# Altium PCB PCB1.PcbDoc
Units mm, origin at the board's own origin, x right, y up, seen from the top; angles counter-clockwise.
Board outline 160 x 100 mm, 4 copper layers (Top Layer, Top inner, Bottom inner, Bottom Layer), stack 1.538 mm thick; 114 components, 70 nets, 377 pads, 75 vias.
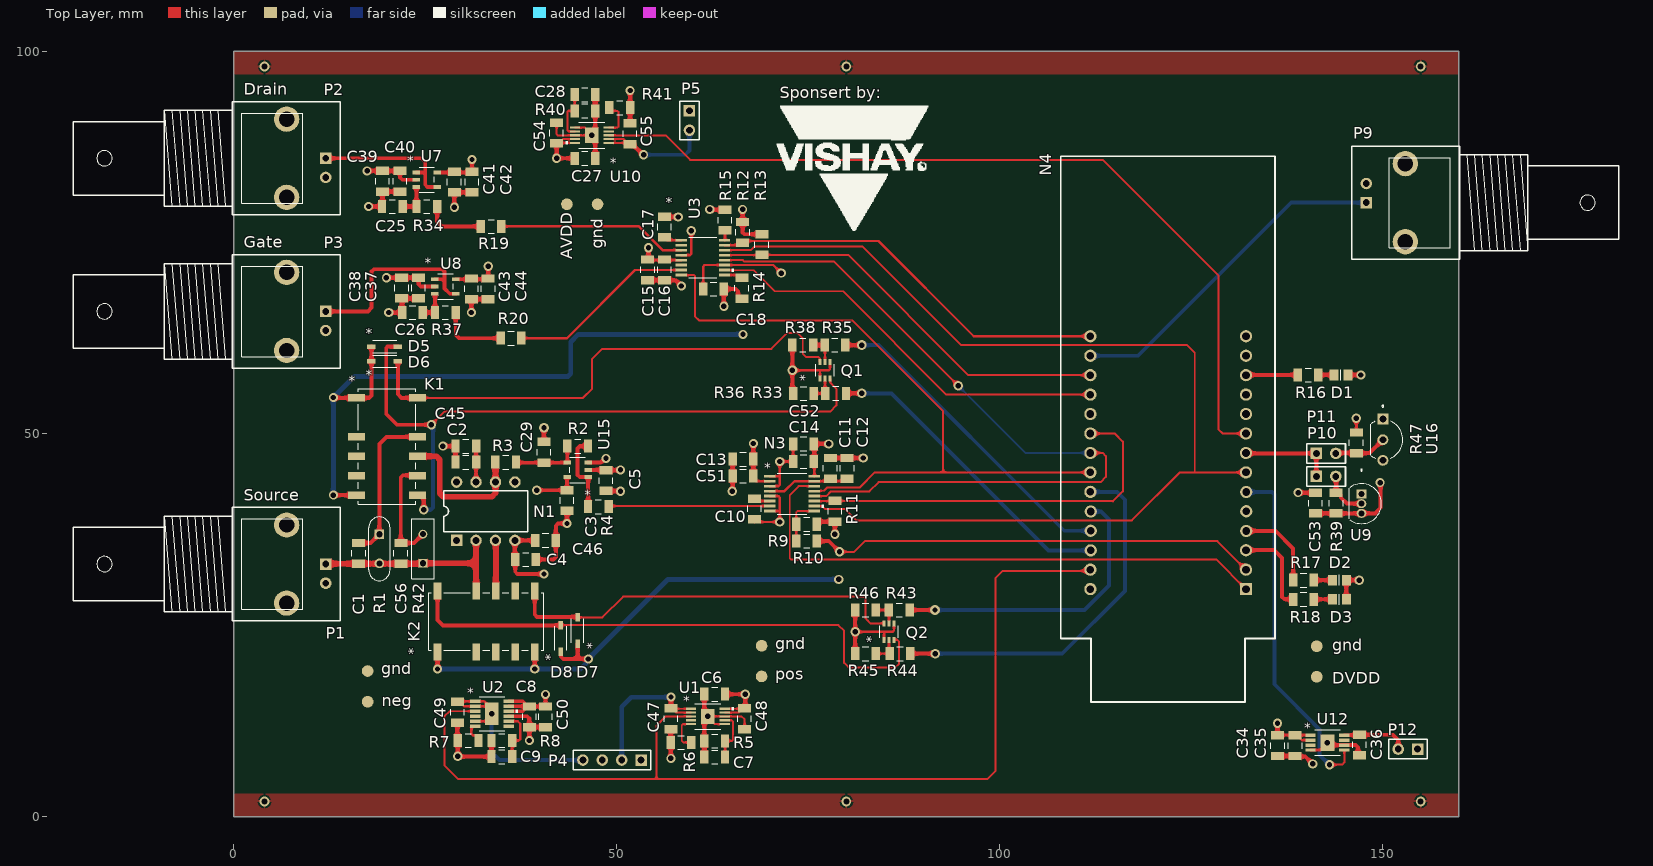
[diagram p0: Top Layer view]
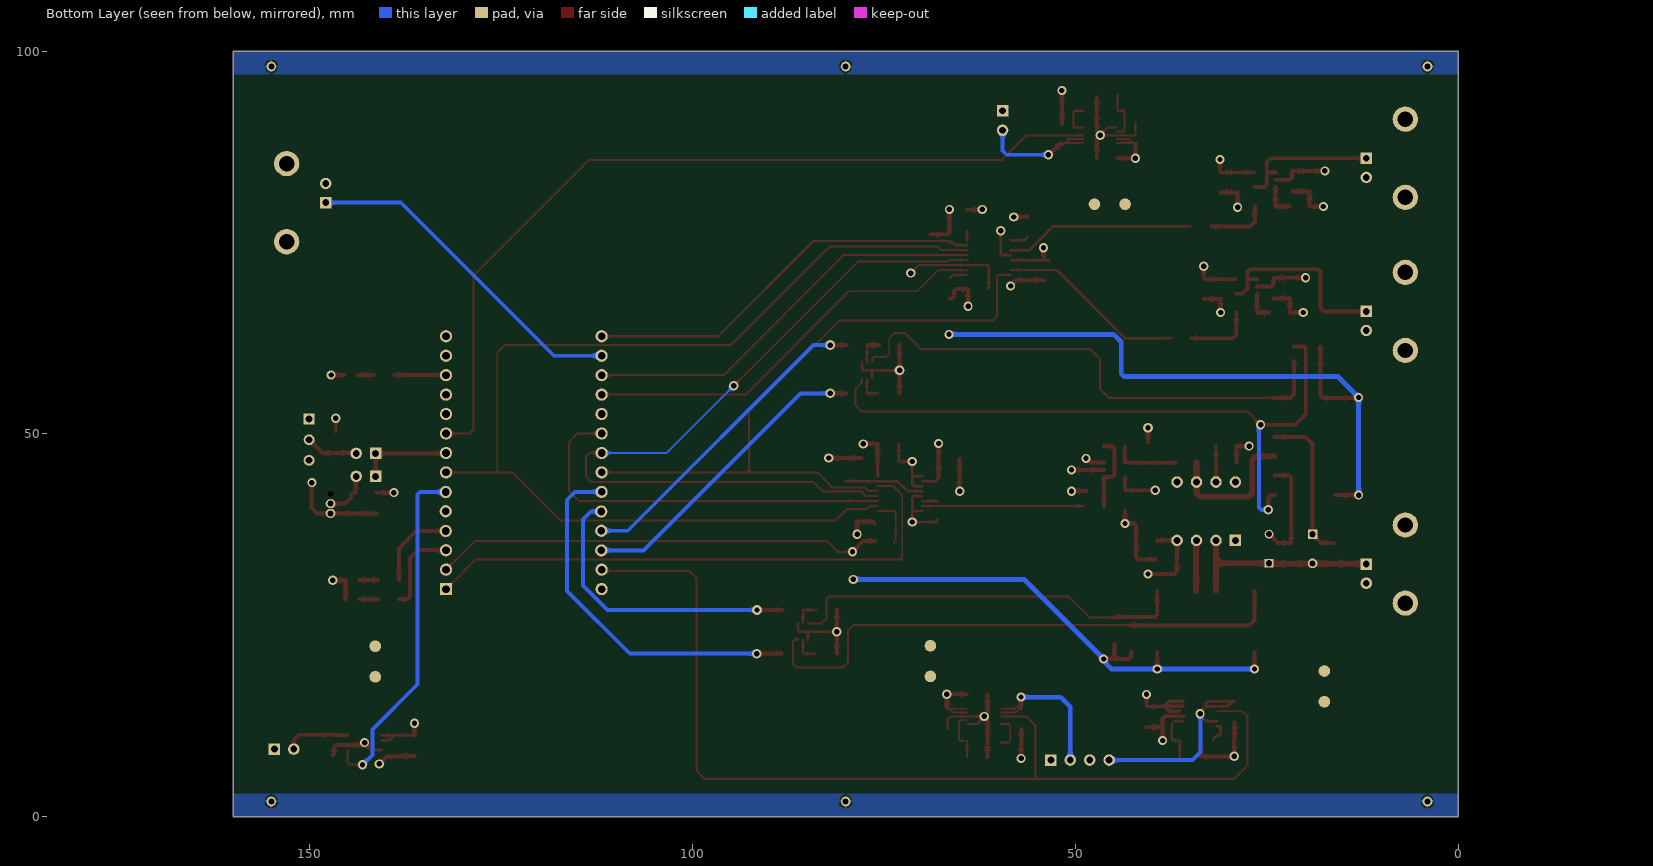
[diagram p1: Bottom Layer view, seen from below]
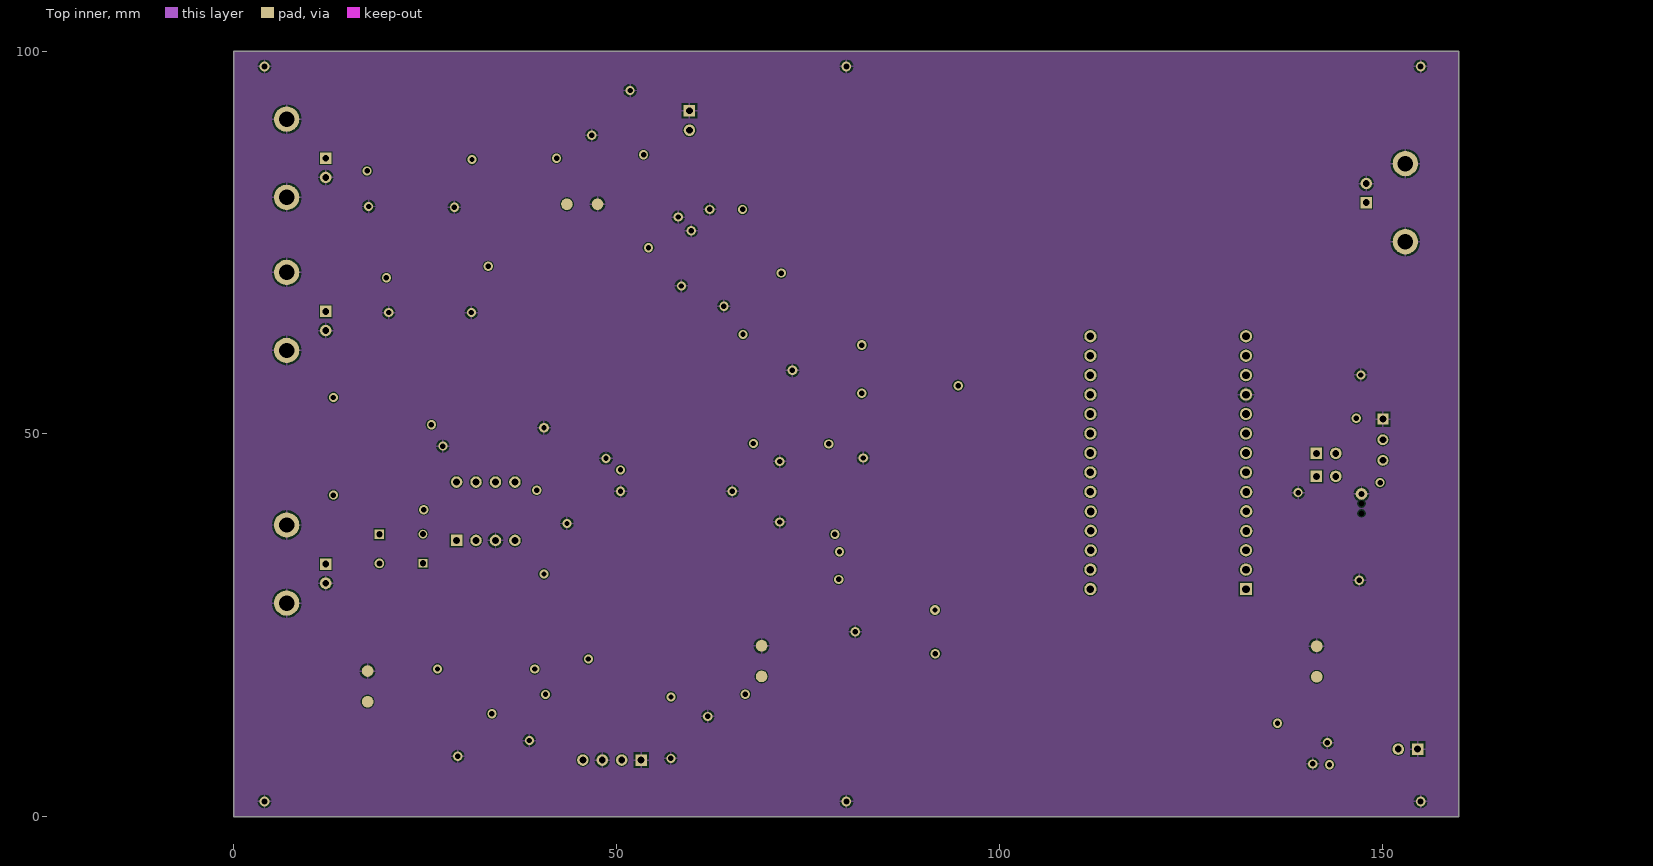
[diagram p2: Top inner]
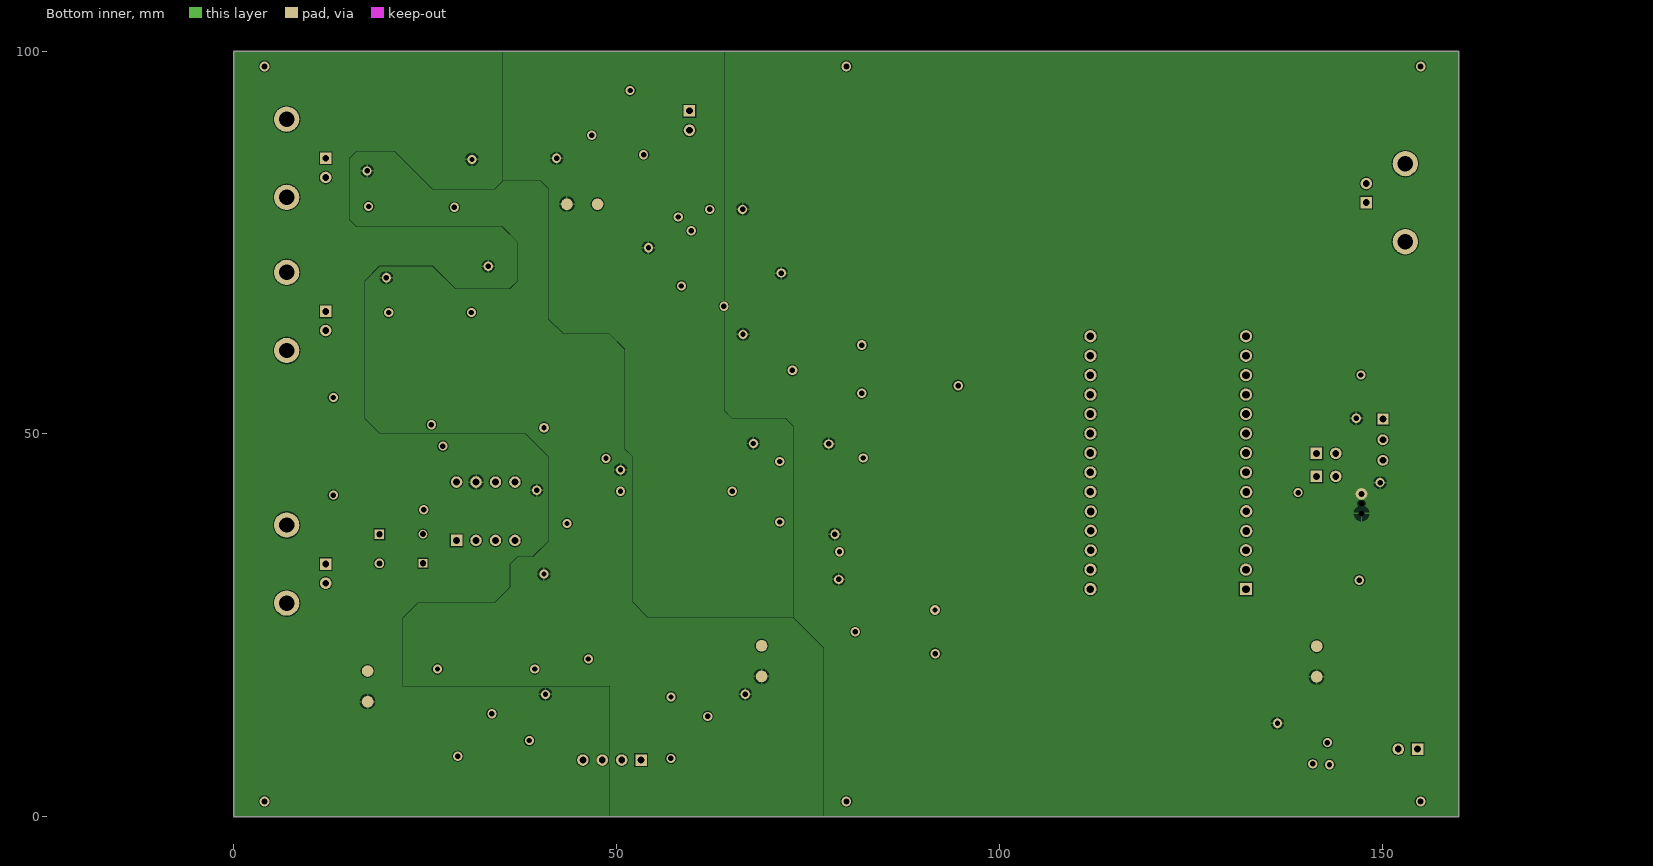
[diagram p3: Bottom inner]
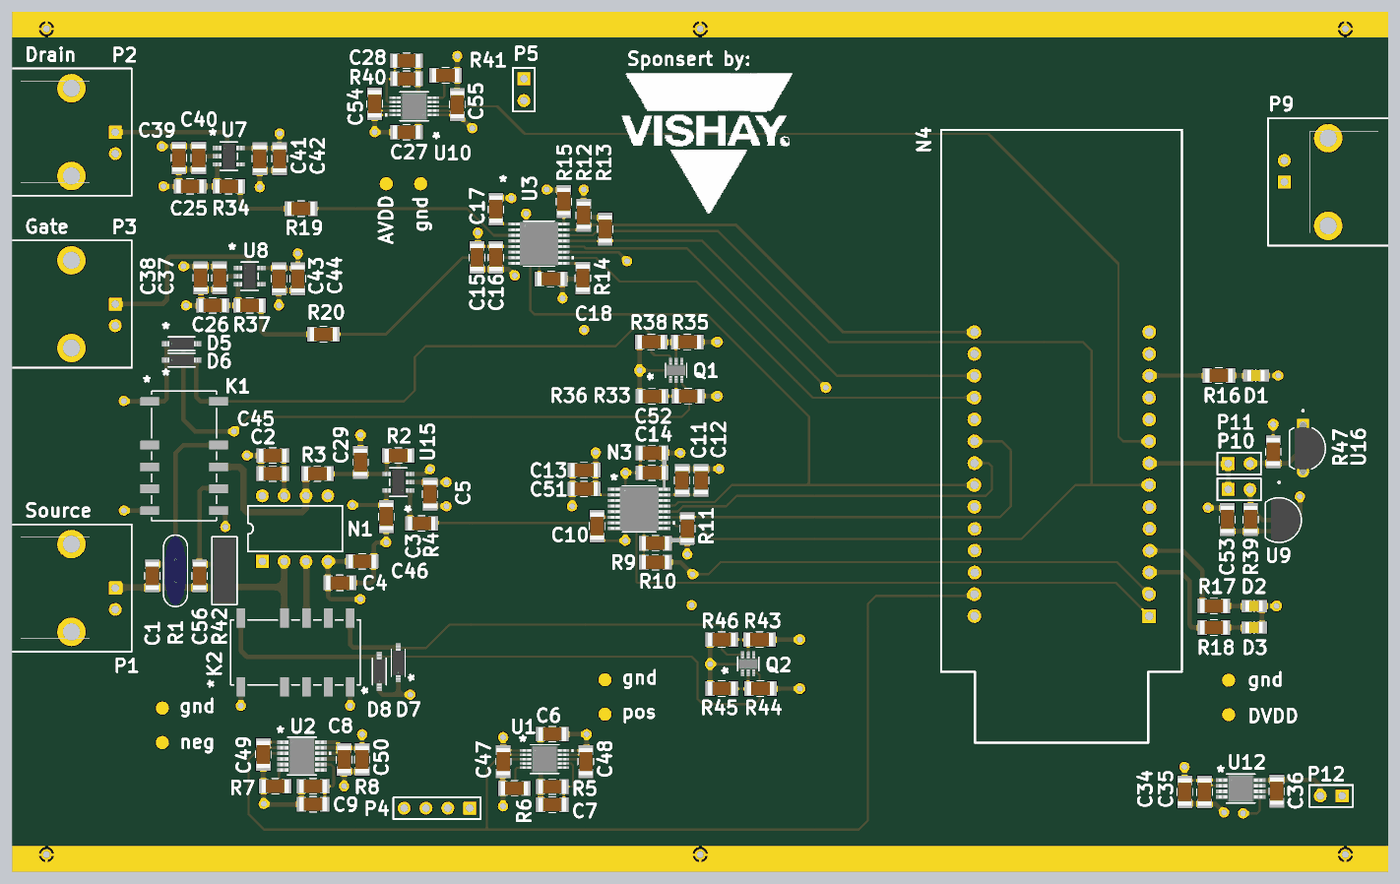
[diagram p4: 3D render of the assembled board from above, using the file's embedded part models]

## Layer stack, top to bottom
Top Solder: solder mask 0.0102, Solder Resist, Dk 3.5
Top Layer: signal copper 0.0356
Dielectric 4: prepreg 0.1524, PP-006, Dk 4.4
Top inner: signal copper 0.035
Dielectric 1: dielectric 1.0922, FR-4, Dk 4.8
Bottom inner: signal copper 0.035
Dielectric 5: prepreg 0.1524, PP-006, Dk 4.4
Bottom Layer: signal copper 0.0356
Bottom Solder: solder mask 0.0102, Solder Resist, Dk 3.5

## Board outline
0,0 160,0 160,100 0,100

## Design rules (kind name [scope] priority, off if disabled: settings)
Clearance [All] p1: gap=0.127 ignorepadtopadclearanceinfootprint=TRUE except(0.025: THPad-THPad)
MinimumSolderMaskSliver THT_21-0248A_Q3-1_MXM [HasFootprint('21-0248A_Q3-1_MXM')] p1: minsoldermaskwidth=0
MinimumSolderMaskSliver [All] p2: minsoldermaskwidth=0.127
PolygonConnect [All] p1: connectstyle=Relief reliefconductorwidth=0.254 reliefentries=4 polygonreliefangle="90 Angle" airgapwidth=0.254
RoutingVias [All] p1: holewidth=0.6 width=1.2 viastyle="Through Hole" minholewidth=0.3 minwidth=0.6 maxholewidth=1 maxwidth=2
SilkToSolderMaskClearance SilkToSolderMaskClearance_1 [HasFootprint('BNC_RA CON')] p1: minsilkscreentomaskgap=0 clearancetoexposedcopper=TRUE
SilkToSolderMaskClearance [IsPad] p2: minsilkscreentomaskgap=0.127 clearancetoexposedcopper=TRUE
SolderMaskExpansion [All] p1: expansion=0.102 istentingtop=FALSE
Width Source [InNet('M_source')] p1: maxlimit=2.54 minlimit=0.254 preferedwidth=0.762
Width Width_1 [All] p2: maxlimit=0.762 minlimit=0.254 preferedwidth=0.762
28 further rules are at their usual default settings.

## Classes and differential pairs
component class U_Cal: Q1 Q2 R33 R35 R36 R38 R43 R44 R45 R46
component class U_Digital_Psu: C34 C35 C36 U12
component class U_Analog_PSU_5: C27 C28 C54 R40 R41 U10
component class U_Temp_Sensors: C53 P10 P11 R39 R47 U9 U16
component class U_Source_TIA: C1 C2 C3 C4 C5 C29 C45 C46 C56 D5 D6 D7 D8 K1 K2 N1 R1 R2 R3 R4 R42 U15
component class U_OPV_psu: C6 C7 C8 C9 C47 C48 C49 C50 R5 R6 R7 R8 U1 U2
component class U_DAC_Buffer_Filter: C25 C26 C37 C38 C39 C40 C41 C42 C43 C44 R19 R20 R34 R37 U7 U8
component class U_CortexM3_dev: D1 D2 D3 N4 R16 R17 R18
component class U_ADC_8681: C10 C11 C12 C13 C14 C51 C52 N3 R9 R10 R11
component class U_AD_5689_DAC: C15 C16 C17 C18 R12 R13 R14 R15 U3
component class Top_Sheet: C55 P1 P2 P3 P4 P5 P9 P12

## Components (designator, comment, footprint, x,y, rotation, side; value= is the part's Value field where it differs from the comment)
C1 "22pF" C1206-KUE 16.3,34.4 r90 top
C2 "100nF" C1206-KUE 30.3,46.3 r0 top
C3 "100nF" C1206-KUE 43.503,41.3 r90 top
C4 "100nF" C1206-KUE 38.1,33.6 r180 top
C5 "100nF" C1206-KUE 48.603,43.9 r90 top
C6 "10uF" C1206-KUE 62.8,16 r0 top
C7 "4.7uF" C1206-KUE 62.8,7.8 r0 top
C8 "10uF" C1206-KUE 38.6,13.049 r90 top
C9 "4.7uF" C1206-KUE 35,7.849 r0 top
C10 "10uF" C1206-KUE 68,40.2 r90 top
C11 "100nF" C1206-KUE 77.9,45.5 r270 top
C12 "10uF" C1206-KUE 80.1,45.5 r270 top
C13 "100nF" C1206-KUE 66.5,46.7 r0 top
C14 "100nF" C1206-KUE 74.4,46.4 r0 top
C15 "10uF" C1206-KUE 54.05,71.425 r90 top
C16 "100nF" C1206-KUE 56.25,71.425 r90 top
C17 "100nF" C1206-KUE 56.25,77.025 r270 top
C18 "100nF" C1206-KUE 62.65,68.925 r180 top
C25 "1uF" C1206-KUE 20.7,79.7 r0 top
C26 "1uF" C1206-KUE 23.324,65.85 r0 top
C27 "10uF" C1206-KUE 45.849,86 r180 top
C28 "4.7uF" C1206-KUE 45.849,94.3 r180 top
C29 "" C1206-KUE 40.5,47.6 r270 top
C34 "100nF" C1206-KUE 136.323,9.279 r90 top
C35 "10uF" C1206-KUE 138.623,9.279 r90 top
C36 "4.7uF" C1206-KUE 147.023,9.379 r90 top
C37 "100nF" C1206-KUE 24.124,69.05 r90 top
C38 "1uF" C1206-KUE 21.924,69.05 r90 top
C39 "100nF" C1206-KUE 19.4,83 r90 top
C40 "1uF" C1206-KUE 21.7,83 r90 top
C41 "100nF" C1206-KUE 28.8,82.9 r90 top
C42 "1uF" C1206-KUE 31.1,82.9 r90 top
C43 "100nF" C1206-KUE 31.024,68.95 r90 top
C44 "1uF" C1206-KUE 33.224,68.95 r90 top
C45 "10uF" C1206-KUE 30.3,48.4 r0 top
C46 "10uF" C1206-KUE 40.7,36.1 r0 top
C47 "10uF" C1206-KUE 57.1,12.8 r90 top
C48 "100nF" C1206-KUE 66.7,12.8 r90 top
C49 "10uF" C1206-KUE 29.2,13.649 r90 top
C50 "100nF" C1206-KUE 40.7,13.049 r90 top
C51 "10uF" C1206-KUE 66.5,44.5 r0 top
C52 "10uF" C1206-KUE 74.4,48.7 r0 top
C53 "1uF" C1206-KUE 141.277,40.961 r270 top
C54 "100nF" C1206-KUE 42.149,89.3 r270 top
C55 "100nF" C1206-KUE 51.749,89.2 r270 top
C56 "22pF" C1206-KUE 21.8,34.4 r90 top
D1 "GREEN" 6-0805_N-KUE 144.6,57.7 r0 top
D2 "GREEN" 6-0805_N-KUE 144.4,30.9 r0 top
D3 "RED" 6-0805_N-KUE 144.4,28.4 r0 top
D5 "1N4148W-7" SOD123_DIO 19.7,61.4 r0 top
D6 "1N4148W-7" SOD123_DIO 19.7,59.5 r0 top
D7 "1N4148W-7" SOD123_DIO 44.9,24.3 r90 top
D8 "1N4148W-7" SOD123_DIO 42.7,23.3 r90 top
K1 "G6SK-2F-TR DC3" "RELAY_G6SK-2F DC3_OMR" 24,42 r0 top
K2 "G6SK-2F-TR DC3" "RELAY_G6SK-2F DC3_OMR" 39.3,29.5 r90 top
N1 "LMC6001AIN/NOPB" DIP8 32.9,39.9 r0 top
N3 "ADS8681IPW" PW16_TEX 72.9,42.2 r0 top
N4 "STM32F103" DIP28 136,15 r180 top
P1 "BNC" "BNC_RA CON" 12,33 r0 top
P2 "BNC" "BNC_RA CON" 12,86 r0 top
P3 "BNC" "BNC_RA CON" 12,66 r0 top
P4 "Header 4" HDR1X4 53.2,7.4 r180 top
P5 "Header 2" HDR1X2 59.5,92.2 r270 top
P9 "BNC" "BNC_RA CON" 147.9,80.2 r180 top
P10 "Header 2" HDR1X2 141.377,44.461 r0 top
P11 "Header 2" HDR1X2 141.377,47.461 r0 top
P12 "Header 2" HDR1X2 154.617,8.821 r180 top
Q1 "2N7002DW" SC-88SC70-6SOT-363_419B-02_ONS_OSI 77.2,58.3 r90 top
Q2 "2N7002DW" SC-88SC70-6SOT-363_419B-02_ONS_OSI 85.575,24.175 r90 top
R1 "CNS020-10MP" RES_CNS020_VIS 19,36.9 r270 top
R2 "10k" C1206-KUE 44.903,48.4 r180 top
R3 "33k" C1206-KUE 35.5,46.3 r180 top
R4 "10" C1206-KUE 47.603,40.5 r180 top
R5 "78.7k" C1206-KUE 62.8,9.9 r180 top
R6 "0" C1206-KUE 58.4,9.7 r180 top
R7 "0" C1206-KUE 30.6,9.949 r180 top
R8 "78.7k" C1206-KUE 35,9.949 r180 top
R9 "10k" C1206-KUE 74.8,38.2 r180 top
R10 "1k" C1206-KUE 74.8,36 r180 top
R11 "4.7k" C1206-KUE 78.5,39.9 r90 top
R12 "4.7k" C1206-KUE 66.45,76.325 r270 top
R13 "4.7k" C1206-KUE 68.95,74.725 r270 top
R14 "10k" C1206-KUE 66.35,69.025 r270 top
R15 "10k" C1206-KUE 64.15,77.925 r90 top
R16 "3.9k" C1206-KUE 140.3,57.7 r0 top
R17 "3.9k" C1206-KUE 139.7,30.9 r0 top
R18 "2.7k" C1206-KUE 139.7,28.4 r0 top
R19 "0" C1206-KUE 33.6,77.1 r180 top
R20 "0" C1206-KUE 36.2,62.5 r180 top
R33 "1k" C1206-KUE 78.6,55.3 r0 top
R34 "10k" C1206-KUE 25.2,79.7 r180 top
R35 "1k" C1206-KUE 78.5,61.6 r0 top
R36 "10k" C1206-KUE 74.4,55.275 r180 top
R37 "10k" C1206-KUE 27.624,65.85 r180 top
R38 "10k" C1206-KUE 74.3,61.6 r180 top
R39 "4.7k" C1206-KUE 143.977,40.961 r90 top
R40 "49.9k" C1206-KUE 45.849,92.2 r0 top
R41 "0" C1206-KUE 50.4,92.6 r0 top
R42 "Y0062100K000T9L" RES_S102K_7P62X2P67_VIS 24.7,33.1 r90 top
R43 "1k" C1206-KUE 86.9,27 r180 top
R44 "1k" C1206-KUE 87,21.3 r0 top
R45 "10k" C1206-KUE 82.5,21.3 r180 top
R46 "10k" C1206-KUE 82.5,27 r180 top
R47 "1k" C1206-KUE 146.604,48.834 r270 top
U1 "LT3042EMSE#TRPBF" 05-08-1664_ADI 61.9,13.1 r0 top
U2 "LT3094EMSE#TRPBF" MSE_05-08-1666_ADI 33.7,13.449 r0 top
U3 "AD5689RBRUZ" RU_16_ADI 61.25,73.025 r0 top
U7 "OPA197IDBVR" DBV5_TEX 25.2,83.2 r0 top
U8 "OPA197IDBVR" DBV5_TEX 27.624,69.25 r0 top
U9 "DS18B20+" 21-0248A_Q3-1_MXM 147.277,42.161 r270 top
U10 "LT3042EMSE#TRPBF" 05-08-1664_ADI 46.749,89 r180 top
U12 "TLV76733DGNR" VSSOP8_DGN_TEX 142.823,9.679 r0 top
U15 "OPA197IDBVR" DBV5_TEX 44.903,45.3 r180 top
U16 "DS28E07+T" 21-0250_Q3+4_MXM 150.073,51.927 r270 top

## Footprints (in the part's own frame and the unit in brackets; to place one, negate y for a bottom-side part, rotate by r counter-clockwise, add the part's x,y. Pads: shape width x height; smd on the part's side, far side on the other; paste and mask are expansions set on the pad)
05-08-1664_ADI [mil]
  rect 52.28x11 smd paste+0 mask+0: 1(-87.14,39.37) 2(-87.14,19.69) 3(-87.14,0) 4(-87.14,-19.68) 5(-87.14,-39.37) 6(87.14,-39.37) 7(87.14,-19.68) 8(87.14,0) 9(87.14,19.69) 10(87.14,39.37)
  rect 70x78 smd paste+0 mask+0: 11(0,0)
  silkscreen extent -66,-66 133,66, body extent -99,-61 99,61, height 43
6-0805_N-KUE [mm] "Chip Resistor, Body 2.0x1.2mm, IPC Medium Density"
  rect 1.2x1.4 smd: 1(-0.9,0) 2(0.9,0)
  silkscreen extent 0,-0.69 0,0.69, body extent -1,-0.63 1,0.63, height 0.8
21-0248A_Q3-1_MXM [mm]
  rect 1.168x1.27 / inner round 1.524 / far side rect 1.168x0 hole 0.8 paste-0.635 mask+0: 1(0,0)
  oval 1.168x1.27 / inner oval 1.524x0 / far side oval 1.168x1.27 hole 0.8 paste-0.635 mask+0: 2(1.27,0) 3(2.54,0)
  silkscreen extent -3.24,-1.59 3.87,2.6, body extent -1.21,-0.95 3.75,2.48, height 4.95
21-0250_Q3+4_MXM [mil]
  rect 56x56 hole 35 paste-28 mask+0: 1(0,0)
  round 56 hole 35 paste-28 mask+0: 2(105.91,0) 3(211.81,0)
  silkscreen extent -72,-62 200,102, body extent -12,-37 224,98, height 195
"BNC_RA CON" [mm] "Connector; BNC Elbow"
  rect 1.5x1.5 hole 0.9: 1(0,0)
  round 3.3 hole 2: 2(-5.1,-5.1) 2(-5.1,5.1)
  round 1.5 hole 0.9: 2(0,-2.5)
  silkscreen extent -33,-7.4 1.9,7.4
C1206-KUE [mm] "Chip Capacitor, Body 3.2x1.6mm, IPC High Density"
  rect 1.1x1.7 smd: 1(-1.35,0) 2(1.35,0)
  silkscreen extent -0.4,-0.9 0.4,0.9, body extent -1.6,-0.8 1.6,0.8, height 0.95
DBV5_TEX [mil]
  rect 38.5x20 smd paste+0 mask+0: 1(-53.75,37.4) 2(-53.75,0) 3(-53.75,-37.4) 4(53.75,-37.4) 5(53.75,37.4)
  silkscreen extent -40,-65 39,65, body extent -59,-60 59,60, height 57
DIP8 [mm] "DIP; 8 Leads; Row Spacing 7.62 mm; Pitch 2.54 mm"
  rect 1.5x1.5 hole 0.9: 1(-3.81,-3.81)
  round 1.5 hole 0.9: 2(-1.27,-3.81) 3(1.27,-3.81) 4(3.81,-3.81) 5(3.81,3.81) 6(1.27,3.81) 7(-1.27,3.81) 8(-3.81,3.81)
  silkscreen extent -5.5,-2.65 5.5,2.65
DIP28 [mm]
  round 1.6 hole 1: 1(24.13,-47.752) 2(24.13,-45.212) 3(24.13,-42.672) 4(24.13,-40.132) 5(24.13,-37.592) 6(24.13,-35.052) 7(24.13,-32.512) 8(24.13,-29.972) 9(24.13,-27.432) 10(24.092,-24.868) 11(24.092,-22.349) 12(24.092,-19.788) 13(24.13,-17.272) 14(24.13,-14.732) 15(3.81,-47.752) 16(3.81,-45.212) 17(3.81,-42.672) 18(3.81,-40.132) 19(3.81,-37.592) 20(3.81,-35.052) 21(3.81,-32.512) 22(3.81,-29.972) 23(3.772,-27.408) 24(3.772,-24.889) 25(3.772,-22.328) 26(3.81,-19.812) 27(3.81,-17.272)
  rect 1.6x1.6 hole 1: 28(3.81,-14.732)
  silkscreen extent 0,-71.26 28,0
HDR1X2 [mm] "Connector; Header; 2 Position"
  rect 1.5x1.5 hole 0.9: 1(0,0)
  round 1.5 hole 0.9: 2(2.54,0)
  silkscreen extent -1.27,-1.27 3.81,1.27
HDR1X4 [mm] "Connector; Header; 4 Position"
  rect 1.5x1.5 hole 0.9: 1(0,0)
  round 1.5 hole 0.9: 2(2.54,0) 3(5.08,0) 4(7.62,0)
  silkscreen extent -1.27,-1.27 8.89,1.27
MSE_05-08-1666_ADI [mil]
  rect 54.56x16.97 smd paste+0 mask+0: 1(-86,63.98) 2(-86,38.39) 3(-86,12.8) 4(-86,-12.8) 5(-86,-38.39) 6(-86,-63.98) 7(86,-63.98) 8(86,-38.39) 9(86,-12.8) 10(86,12.8) 11(86,38.39) 12(86,63.98)
  rect 69x116 smd paste-57.5 mask+0: 13(0,0)
  silkscreen extent -66,-87 133,86, body extent -99,-81 99,81, height 43
PW16_TEX [mil]
  rect 58x14 smd paste+0 mask+0: 1(-115,89.57) 2(-115,63.98) 3(-115,38.39) 4(-115,12.8) 5(-115,-12.79) 6(-115,-38.39) 7(-115,-63.98) 8(-115,-89.57) 9(115,-89.57) 10(115,-63.98) 11(115,-38.39) 12(115,-12.8) 13(115,12.8) 14(115,38.39) 15(115,63.98) 16(115,89.57)
  silkscreen extent -76,-106 164,105, body extent -130,-101 130,101, height 47
"RELAY_G6SK-2F DC3_OMR" [mil]
  rect 87x39 smd paste+0 mask+0: 1(-314.96,500) 3(-314.96,300) 4(-314.96,200) 5(-314.96,100) 6(-314.96,0) 7(0,0) 8(0,100) 9(0,200) 10(0,300) 12(0,500)
  silkscreen extent -306,-46 -9,546
RES_CNS020_VIS [mm]
  rect 1.27x1.27 hole 0.8 paste-0.635 mask+0: 1(0,0)
  round 1.27 hole 0.8 paste-0.635 mask+0: 2(3.81,0)
  silkscreen extent -2.26,-1.4 6.07,1.4, body extent -2.13,-1.27 5.94,1.27, height 6.6
RES_S102K_7P62X2P67_VIS [mil]
  rect 45x45 hole 31.5 paste-22.5 mask+0: 1(0,0)
  round 45 hole 31.5 paste-22.5 mask+0: 2(150,0)
  silkscreen extent -80,-57 230,58, body extent -75,-53 225,53, height 336
RU_16_ADI [mm]
  rect 1.461x0.351 smd paste+0 mask+0: 1(-2.825,2.275) 2(-2.825,1.625) 3(-2.825,0.975) 4(-2.825,0.325) 5(-2.825,-0.325) 6(-2.825,-0.975) 7(-2.825,-1.625) 8(-2.825,-2.275) 9(2.825,-2.275) 10(2.825,-1.625) 11(2.825,-0.975) 12(2.825,-0.325) 13(2.825,0.325) 14(2.825,0.975) 15(2.825,1.625) 16(2.825,2.275)
  silkscreen extent -1.81,-2.63 4.06,2.63, body extent -3.2,-2.5 3.2,2.5, height 1.2
SC-88SC70-6SOT-363_419B-02_ONS_OSI [mm]
  rect 0.782x0.355 smd paste+0 mask+0: 1(-1.064,0.65) 2(-1.064,0) 3(-1.064,-0.65) 4(1.064,-0.65) 5(1.064,0) 6(1.064,0.65)
  silkscreen extent -0.8,-1.23 0.8,1.23, body extent -1.1,-1.1 1.1,1.1, height 1.09
SOD123_DIO [mm]
  rect 1.111x0.601 smd paste+0 mask+0: 1(-1.725,0) 2(1.725,0)
  silkscreen extent -1.55,-0.8 1.55,0.8, body extent -1.92,-0.67 1.92,0.67, height 0.81
VSSOP8_DGN_TEX [mil]
  rect 52.5x17 smd paste+0 mask+0: 1(-87.25,38.38) 2(-87.25,12.79) 3(-87.25,-12.8) 4(-87.25,-38.39) 5(87.25,-38.39) 6(87.25,-12.8) 7(87.25,12.79) 8(87.25,38.38)
  rect 73x85 smd paste+0 mask+0: EPAD(0,0)
  silkscreen extent -66,-66 66,66, body extent -99,-61 99,61, height 43

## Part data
C1 C2 C3 C4 C5 C6 C7 C8 C9 C10 C11 C12 C13 C14 C15 C16 C17 C18 C25 C26 C27 C28 C29 C34 C35 C36 C37 C38 C39 C40 C41 C42 C43 C44 C45 C46 C47 C48 C49 C50 C51 C52 C53 C54 C55 C56: library part Capacitor, "Capacitor", Manufacturer=Kemet
D1 D2 D3: library part LED0, "Typical INFRARED GaAs LED"
D5 D6 D7 D8: "Description", Manufacturer_Name="Diodes Inc"
K1 K2: "Description", Manufacturer_Name=Omron
N1: library part LMC6001AINNOPB, "Ultra-Low Input Current Amplifier 8-PDIP -40 to 85", Manufacturer=NationalSemiconductor, Manufacturer_Name="Texas Instruments", PartNumber=LMC6001AIN
N3: "16-bit, 1MSPS 1-ch SAR ADC with programmable (Â±12V, Â±10V, Â±6V, Â±5V, Â±2.5V) input ranges on 5V supply 16-TSSOP -40 to 125", Manufacturer_Name="Texas Instruments"
P1 P2 P3 P9: "BNC Elbow Connector"
P4: "Header, 4-Pin"
P5 P10 P11 P12: "Header, 2-Pin"
Q1 Q2: "Description", Manufacturer_Name=onsemi
R1: library part CNS020-10KP, "CNS 020 10K 0,02% e2", Manufacturer_Name=Vishay
R2 R3 R4 R5 R6 R7 R8 R9 R10 R11 R12 R13 R14 R15 R16 R17 R18 R19 R20 R33 R34 R35 R36 R37 R38 R39 R40 R41 R43 R44 R45 R46 R47: library part ResistorSMD, "Resistor SMD", Manufacturer=AVX
R42: "No Description Available", Manufacturer_Name=Vishay
U1 U10: library part LT3042EMSETRPBF, "20V, 200mA, Ultralow Noise, Ultrahigh PSRR RF Linear Regulator", Manufacturer_Name="Analog Devices Inc"
U2: library part LT3094EMSETRPBF, "âˆ’20V, 500mA, Ultralow Noise, Ultrahigh PSRR Negative Linear Regulator", Manufacturer_Name="Analog Devices Inc"
U3: "Dual, 16-Bit nanoDAC+ with 2 ppm/Â°C Reference, SPI Interface", Manufacturer_Name="Analog Devices Inc"
U7 U8 U15: "Single, 36-V, precision, rail-to-rail input output, low offset voltage op amp 5-SOT-23 -40 to 125", Manufacturer_Name="Texas Instruments"
U9: "Programmable Resolution 1-Wire Digital Thermometer", Manufacturer_Name="Analog Devices Inc"
U12: "Adjustable- and fixed-output, 1-A, 16-V, positive-voltage low-dropout (LDO) linear regulator 8-HVSSOP -40 to 125", Manufacturer_Name="Texas Instruments"
U16: "1024-Bit, 1-Wire EEPROM", Manufacturer_Name="Analog Devices Inc"

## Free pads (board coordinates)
  round 1.524 all layers, no hole: 16(17.473,15.027) 16(17.473,19.027) 16(43.5,80) 16(47.5,80) 16(68.927,18.327) 16(68.927,22.327) 16(141.427,18.273) 16(141.427,22.273)

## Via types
v1: diameter 1.2, hole 0.7, Top Layer to Bottom Layer, 60 vias
v2: diameter 1.27, hole 0.7, Top Layer to Bottom Layer, 9 vias
v3: diameter 1.27, hole 0.8, Top Layer to Bottom Layer, 6 vias

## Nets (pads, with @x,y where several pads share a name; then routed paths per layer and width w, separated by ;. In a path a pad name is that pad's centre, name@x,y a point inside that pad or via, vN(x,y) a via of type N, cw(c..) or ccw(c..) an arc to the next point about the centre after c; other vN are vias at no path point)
AVDD: C13.2 C15.2 C16.2 C27.2 C51.2 C54.2 N3.2 pad.16@43.5,80 U3.5 U10.9 U10.10 | length 22.4
  Top Layer w0.254: C54.2@42.199,88 C54.2@42.499,88 ; U10.10 C54.2@42.499,88 ; U10.9 42.999,88.5 C54.2@42.499,88
  Top Layer w0.305: C15.2@53.425,72.7 C15.2@54.125,72.7 ; C15.2 C15.2@54.125,72.7 ; U3.5 C15.2@54.125,72.7 ; C51.2 67.85,44.223 68.248,43.825 N3.2
  Top Layer w0.508: C54.2 v1(42.149,86) C27.2 ; C15.2 54.15,72.875 v1(54.15,74.325) ; C51.2 C13.2 v1(67.85,48.75)
damper_out: R2.1 R4.2 U15.1 | length 10.3
  Top Layer w0.508: R4.2 46.269,40.515 U15.1 45.201,44.35 44.903,44.648 44.903,48.102 45.201,48.4 R2.1
DVDD: C14.2 C18.2 C34.2 C35.2 C52.2 C53.2 D5.1 D6.1 D7.1 D8.1 K1.1 K1.6 K2.1 K2.6 N3.16 pad.16@141.427,18.273 R9.1 R11.1 R12.1 R13.1 R39.1 R47.1 U3.11 U9.3 U12.1 U12.2 | length 206.6
  Top Layer w0.305: C18.2 61.3,71.871 61.479,72.05 U3.11 70.45,72.05 v1(71.5,71) ; C52.2 C52.2@75.821,48.629 ; N3.16 C14.2@75.821,46.329 ; R9.1 R9.1@76.5,38.55 ; C34.2 136.348,10.653 U12.1 ; C35.2 138.923,10.629 139.32,10.231 139.32,10.182 139.499,10.003 U12.2 ; R47.1 v2(146.604,52.034)
  Top Layer w0.508: v1(13,42) K1.6 ; v1(13,54.75) 13.05,54.7 K1.1 17.677,54.7 17.975,54.998 D6.1 D5.1 ; v1(26.6,19.3) K2.1 ; v1(39.3,19.3) K2.6 ; D8.1 42.746,21.529 42.746,20.898 43.044,20.6 44.9,20.6 ; D7.1 44.9,20.6 ; v1(46.3,20.6) 44.9,20.6 ; v1(66.45,79.325) R12.1 66.45,76.325 66.7,76.075 R13.1 ; C14.2 C14.2@75.821,46.329 ; C52.2 v1(77.7,48.7) ; C14.2@75.821,46.4 C52.2@75.821,48.629 ; R9.1@76.5,38.55 R11.1 v1(78.5,36.9) ; v1(136.3,12.2) 136.3,10.651 C34.2 ; C53.2 R39.1 147.267,39.611 U9.3 149.037,39.621 149.777,40.361 v1@149.777,43.761
  Bottom Layer w0.635: v1(13,42) v1(13,54.75) 15.75,57.5 43.628,57.5 44,57.872 44,62 45,63 v1(66.5,63) ; v1(26.6,19.3) v1(39.3,19.3) 45.3,19.3 45.983,19.983 45.983,20.111 46.3,20.428 v1(46.3,20.6) 56.7,31 v1(79,31)
  other v1: 149.704,43.634
GND: C2.1 C3.1 C4.1 C5.1 C6.1 C7.1 C8.1 C9.1 C10.1 C11.1 C12.1 C13.1 C14.1 C15.1 C16.1 C17.1 C18.1 C25.1 C26.1 C27.1 C28.1 C29.1 C34.1 C35.1 C36.1 C37.1 C38.1 C39.1 C40.1 C41.1 C42.1 C43.1 C44.1 C45.1 C46.2 C47.1 C48.1 C49.1 C50.1 C51.1 C52.1 C53.1 C54.1 C55.1 D1.2 D2.2 D3.2 K2.9 N1.3 N3.1 N3.3 N3.5 N3.8 N4.18 P1.2 P2.2 P3.2 P4.1 P4.3 P5.1 P9.2 P12.1 pad.16@17.473,19.027 pad.16@47.5,80 pad.16@68.927,22.327 pad.16@141.427,22.273 Q1.1 Q1.4 Q2.1 Q2.4 R5.2 R6.2 R7.2 R8.2 R14.2 R15.2 R36.2 R38.2 R40.2 R41.2 R45.2 R46.2 U1.6 U1.8 U1.11 U2.9 U3.4 U9.1 U10.6 U10.8 U10.11 U12.4 U12.6 U12.EPAD U15.3 U16.1 | length 200.5
  Top Layer w0.254: C54.1 42.149,89.149 42.298,89 U10.8 v1(46.749,89) ; U10.6 45.851,90 U10.11@46.749,89.102 ; U1.11@61.9,12.998 62.662,12.236 62.674,12.236 62.811,12.1 U1.6 ; v1(61.9,13.1) U1.8 66.3,13.1 66.7,12.7 C48.1
  Top Layer w0.305: U3.4 59.571,73.35 59.75,73.529 v1(59.75,76.525) ; C10.1@68,38.45 C10.1@68.05,38.5 ; C10.1 68.35,38.5 v1(71.3,38.5) 71.3,40.104 ; N3.8 71.121,39.925 71.3,40.104 ; N3.5 71.121,41.875 71.3,41.696 71.3,40.104 ; N3.3 71.121,43.175 71.3,43.354 v1(71.3,46.4) C14.1 C52.1 ; N3.1 71.121,44.475 ; v2(72.95,58.3) 77.671,58.3 77.85,58.479 Q1.4 ; Q1.1 76.55,58.25 ; v1(81.15,24.15) 86.046,24.15 86.225,24.329 Q2.4@86.225,25.264 ; Q2.1@84.925,23.136 84.925,23.996
  Top Layer w0.432: U12.4 141.848,8.704 v1(142.823,9.679) ; U12.EPAD@142.112,8.815 U12.EPAD@142.823,9.526
  Top Layer w0.508: v1(17.6,79.7) C25.1 19.4,79.75 C39.1 C40.1 ; v1(20.224,65.85) C26.1 21.974,67.65 C38.1 C37.1 ; v1(27.3,48.4) C45.1 C2.1 ; v1(28.8,79.6) C41.1 C42.1 ; C49.1 29.2,9.999 R7.2 v1(29.25,7.899) 29.3,7.849 C9.1 R8.2 ; v1(31.024,65.85) C43.1 C44.1 ; N1.3 N1.3@34.22,36.04 ; U2.9 38.302,13.124 38.6,12.826 C8.1 ; v1(38.6,9.949) C8.1 ; C4.1 41.752,33.6 42.05,33.898 42.05,38.002 42.348,38.3 v1(43.503,38.3) C3.1 ; C29.1 v2(40.5,50.8) ; C50.1 C8.1 ; U15.3 47.925,46.25 48.475,46.8 v1(48.603,46.8) ; v1(46.749,89) 47.199,88.55 C27.1 ; U10.11@46.8,89.051 47.199,89.45 R40.2 C28.1@47.199,94 ; C5.1 48.607,42.547 50.457,42.547 v1(50.503,42.5) ; C55.1 R41.2@51.749,92.15 ; R41.2 v1(51.751,94.849) ; C15.1 C16.1 57.7,70.075 v1(58.45,69.325) ; C17.1 56.275,78.35 58.025,78.35 v1(58.05,78.325) ; v1(57.077,7.623) 57.075,7.625 57.075,9.675 R6.2 57.05,11.4 C47.1 ; C7.1 R5.2 U1.11@61.45,12.65 ; U1.11@61.45,13.55 C6.1 ; v1(62.15,79.325) 62.2,79.275 R15.2 ; v1(64,66.675) C18.1 65.543,68.925 65.841,68.627 65.841,67.971 66.137,67.675 R14.2 ; v1(65.1,42.5) 65.15,42.55 C51.1 C13.1 ; R36.2@72.95,55.3 v2(72.95,58.3) R38.2@72.95,61.475 ; C11.1 C12.1 v1(82.2,46.85) ; R45.2 v1(81.15,24.15) R46.2 ; C34.1 C35.1 ; C35.1@138.623,7.906 138.666,7.863 139.937,7.863 v1(140.9,6.9) ; v1(139.004,42.334) 139.027,42.311 C53.1 ; U12.EPAD@142.823,9.526 v1(142.823,9.679) 143.148,9.353 U12.6 146.525,9.353 146.823,9.056 146.823,8.229 C36.1 ; D3.2 D2.2 v2(147,30.9) ; D1.2 v1(147.2,57.7)
  Top Layer w0.762: K2.9 N1.3@34.22,36.04
  other v3: 4,2 80,2 155,2 4,98 80,98 155,98
M_source: C1.1 C56.1 K2.10 N1.2 P1.1 R1.2 R42.1 | length 26.3
  Top Layer w0.508: R42.1@24.65,33.05 R42.1 ; K2.10@31.58,29.5 K2.10@31.63,29.55
  Top Layer w0.762: P1.1 12.05,33.05 C1.1 C56.1 R42.1@24.65,33.05 ; R42.1 31.63,33.1 ; K2.10@31.63,29.55 31.63,33.1 ; N1.2 31.63,33.1
neg_out: C2.2 C3.2 C8.2 C41.2 C42.2 C43.2 C44.2 C45.2 C50.2 N1.7 pad.16@17.473,15.027 U2.10 U2.11 U2.12 U7.5 U8.5 U15.5 | length 34.6
  Top Layer w0.432: U7.5 31,84.15 C42.2 v1(31.1,85.848) ; U8.5 33.124,70.2 C44.2 v1(33.224,71.898) ; N1.7 31.63,48.38 C45.2 C45.2@31.675,48.425 ; U2.11 C8.2@38.275,14.424 ; U2.12 37.713,15.074 37.966,14.821 37.966,14.733 38.125,14.574 38.425,14.574 38.575,14.424 C8.2 ; U2.10@36.361,13.774 37.713,13.774 37.966,14.027 37.966,14.065 38.3,14.399 C8.2@38.45,14.399 ; C8.2@38.425,14.424 C8.2@38.45,14.399 ; v1(39.55,42.65) C3.2 43.503,44.315 U15.5 ; v1(40.7,15.983) C50.2 C8.2 ; C8.2@38.45,14.399 C8.2
  Top Layer w0.508: C8.2@38.125,14.574 38.275,14.424 38.425,14.424 C8.2@38.575,14.424
NetC1_2: C1.2 K1.10 R1.1 | length 20.4
  Top Layer w0.508: C1.2 17.85,35.75 R1.1 19,48.7 19.92,49.62 K1.10
NetC7_2: C7.2 R5.1 U1.7 | length 6.7
  Top Layer w0.254: U1.7 65,12.6 65.2,12.4 65.2,10.049 65.051,9.9 R5.1 C7.2
NetC9_2: C9.2 R8.1 U2.8 | length 6.9
  Top Layer w0.305: U2.8 37.075,12.474 37.4,12.149 37.4,10.127 37.221,9.949 R8.1 C9.2
NetC17_2: C17.2 U3.1 | length 2.3
  Top Layer w0.305: C17.2 56.625,75.3 U3.1
NetC25_2: C25.2 R34.2 U7.3 | length 4.4
  Top Layer w0.508: C25.2 R34.2 23.85,82.25 U7.3
NetC26_2: C26.2 R37.2 U8.3 | length 4.1
  Top Layer w0.508: C26.2 R37.2 26.274,68.3 U8.3
NetC28_2: C28.2 R40.1 U10.7 | length 6.6
  Top Layer w0.254: C28.2 R40.1 43.698,92.2 43.549,92.051 43.549,89.649 43.698,89.5 U10.7
NetC29_2: C29.2 R2.2 R3.1 U15.4 | length 8.9
  Top Layer w0.432: R3.1 36.9,46.25 U15.4 43.553,46.265 R2.2
NetC36_2: C36.2 P12.2 U12.8 | length 8.6
  Top Layer w0.432: U12.8 146.948,10.653 C36.2
  Top Layer w0.508: C36.2 147.051,10.7 151.4,10.7 152.077,10.023 P12.2
NetC47_2: C47.2 P4.2 U1.1 U1.2 | length 20.5
  Top Layer w0.254: v1(57.089,15.646) v1@57.1,15.634 ; C47.2@57.261,14.15 57.811,13.6 U1.2 ; C47.2@57.4,14.55 57.85,14.1 U1.1
  Top Layer w0.508: C47.2 v1@57.1,15.634
  Bottom Layer w0.635: P4.2 50.66,14.36 51.9,15.6 57.043,15.6 v1(57.089,15.646)
NetC49_2: C49.2 P4.4 U2.1 U2.2 U2.5 U2.13 | length 29.2
  Top Layer w0.305: U2.5 32.976,12.474 U2.13@33.7,13.198 ; U2.13@33.7,13.7 U2.13@32.976,14.424 ; U2.13@32.976,14.424 32.976,14.773 32.675,15.074 U2.1 29.275,15.074 C49.2 29.5,14.999 30.075,14.424 U2.2 U2.13@32.976,14.424
  Bottom Layer w0.508: v1(33.7,13.449) 33.65,13.399 33.65,8.45 34.7,7.4 P4.4
NetC55_2: C55.2 P5.2 U10.1 U10.2 | length 16.6
  Top Layer w0.254: U10.1 C55.2@51.299,88 ; U10.2 50.878,88.5 51.026,88.351 51.026,88.273 C55.2@51.299,88 ; C55.2@51.449,87.85 C55.2@51.299,88 ; C55.2@51.599,88 C55.2@51.299,88
  Top Layer w0.508: C55.2 52.049,87.85 53.439,86.46 v1(53.511,86.46)
  Bottom Layer w0.508: v1(53.511,86.46) 58.96,86.46 59.5,87 P5.2
NetC56_2: C56.2 K1.8 R42.2 | length 14.3
  Top Layer w0.508: K1.8 23.94,44.6 22.098,44.6 21.8,44.302 C56.2 23.54,35.75 R42.2
NetD1_1: D1.1 R16.2 | length 2.1
  Top Layer w0.508: R16.2 D1.1
NetD2_1: D2.1 R17.2 | length 2.5
  Top Layer w0.508: R17.2 D2.1
NetD3_1: D3.1 R18.2 | length 2.5
  Top Layer w0.508: R18.2 D3.1
NetD5_2: D5.2 K1.7 Q1.3 | length 89.3
  Top Layer w0.254: v1(25.8,51.2) 27.5,52.9 77.875,52.9 78.7,53.725 78.7,55.9 78.054,56.546 78.054,56.555 77.9,56.709 77.9,57.186 Q1.3
  Top Layer w0.508: D5.2 20.049,61.4 19.9,61.251 19.9,52.6 21.3,51.2 v1(25.8,51.2) ; K1.7 24.559,42 24.8,41.759 v1(24.8,40.1)
  Bottom Layer w0.508: v1(24.8,40.1) 25.728,40.1 26.026,40.398 26.026,50.787 25.8,51.013 v1(25.8,51.2)
NetD6_2: D6.2 K1.12 Q1.6 | length 68.4
  Top Layer w0.254: K1.12 45.6,54.7 46.8,55.9 46.8,59.8 48.1,61.1 70.2,61.1 72.3,63.2 73.6,63.2 74.3,62.5 74.3,60.451 74.7,60.051 76.351,60.051 76.5,59.902 Q1.6@76.5,59.451
  Top Layer w0.508: D6.2 21.425,55.175 21.9,54.7 K1.12
NetD7_2: D7.2 K2.7 Q2.6 | length 52.9
  Top Layer w0.254: D7.2 48.125,26.025 50.85,28.75 82.25,28.75 82.5,28.5 82.5,25.9 82.8,25.6 83.136,25.264 Q2.6@84.925,25.264
  Top Layer w0.508: K2.7 39.3,26.398 39.598,26.1 D7.2@44.854,26.1
NetD8_2: D8.2 K2.12 Q2.3 | length 73
  Top Layer w0.254: D8.2@42.675,25 D8.2 78.95,25.025 79.7,24.275 79.7,20.1 80.3,19.5 86.4,19.5 86.9,20 86.9,22.875 86.639,23.136 Q2.3@86.225,23.136
  Top Layer w0.508: K2.12 26.6,25.7 27.3,25 D8.2@42.675,25
NetN3_7: N3.7 R4.1 | length 21
  Top Layer w0.305: R4.1@48.953,40.575 N3.7
NetN3_9: N3.9 R9.2 R10.2 | length 6.5
  Top Layer w0.254: R10.2 R9.2 73.45,39.75 73.625,39.925 N3.9 ; R10.2@73.65,35.7 R10.2@73.65,36
NetN3_11: N3.11 N4.6 R11.2 | length 52
  Top Layer w0.254: N3.11 78.475,41.225 R11.2 114.75,41.25 114.8,41.2 116.1,42.5 116.1,49 115.048,50.052 N4.6
NetN3_14: N3.14 N4.28 | length 73.2
  Top Layer w0.254: N3.14 73.775,43.175 72.6,42 72.6,33.75 72.75,33.6 128.322,33.6 N4.28
NetN4_1: N4.1 R12.2 U3.15 | length 53.2
  Top Layer w0.305: U3.15 65.725,74.65 66.15,75.075 R12.2@66.45,75.075 ; R12.2 66.675,75.2 84.2,75.2 96.648,62.752 N4.1
NetN4_2: N4.2 P9.1 | length 44.3
  Bottom Layer w0.508: N4.2 118.112,60.212 138.1,80.2 P9.1
NetN4_3: N4.3 R13.2 U3.13 | length 54.3
  Top Layer w0.254: U3.13 68.925,73.35 R13.2 80.225,73.375 95.928,57.672 N4.3
NetN4_4: N4.4 U3.10 | length 54.5
  Top Layer w0.254: U3.10 64.1,71.375 67.889,71.375 70.632,68.632 72.132,68.632 79.568,68.632 93.068,55.132 N4.4
NetN4_9: N4.9 R44.2 | length 48.3
  Top Layer w0.508: R44.2 v2(91.6,21.3)
  Bottom Layer w0.508: v2(91.6,21.3) 108.2,21.3 116.4,29.5 116.4,41.4 115.368,42.432 N4.9
NetN4_10: N4.10 R43.1 | length 38.8
  Top Layer w0.508: R43.1 v2(91.581,27)
  Bottom Layer w0.508: v2(91.581,27) 111.1,27 114.3,30.2 114.3,38.8 113.232,39.868 N4.10
NetN4_11: N4.11 R35.2 | length 42.1
  Top Layer w0.508: R35.2 v2(82,61.6)
  Bottom Layer w0.508: v2(82,61.6) 84.2,61.6 108.451,37.349 N4.11
NetN4_12: N4.12 R33.2 | length 40.5
  Top Layer w0.508: R33.2 v2(82,55.3)
  Bottom Layer w0.508: v2(82,55.3) 85.9,55.3 106.412,34.788 N4.12
NetN4_13: N4.13 U1.3 U2.3 | length 133.9
  Top Layer w0.254: U2.3 28.174,13.774 27.5,13.1 27.5,6.7 29.3,4.9 55.2,4.9 ; U1.3 56.4,13.1 55.2,11.9 55.2,4.9 ; N4.13 111.698,32.1 100.4,32.1 99.5,31.2 99.5,6 98.4,4.9 55.2,4.9
NetN4_17: N4.17 R16.1 | length 6.9
  Top Layer w0.305: R16.1@138.872,57.622 R16.1
  Top Layer w0.508: N4.17 132.218,57.7 R16.1
NetN4_20: N4.20 U10.3 | length 111.1
  Top Layer w0.254: U10.3 56.4,89 59.6,85.8 113.5,85.8 128.6,70.7 128.6,50.6 129.148,50.052 N4.20
NetN4_21: N4.21 P10.1 P11.1 | length 12.4
  Top Layer w0.508: N4.21@132.241,47.461 P11.1 ; P11.1@141.262,47.346 P11.1 ; P10.1 P11.1
  Bottom Layer w0.508: N4.21 N4.21@132.241,47.461
NetN4_23: N4.23 U12.5 | length 45.8
  Top Layer w0.254: v1(143.1,6.8) 143.105,6.795 144.741,6.795 145.039,7.092 U12.5
  Bottom Layer w0.508: N4.23 135.602,42.408 135.9,42.11 135.9,17.3 141.807,11.393 141.807,8.083 v1@143.09,6.8
NetN4_25: N4.25 R17.1 | length 11.2
  Top Layer w0.508: N4.25 136.072,37.328 138.35,35.05 R17.1
NetN4_26: N4.26 R18.1 | length 11.8
  Top Layer w0.508: N4.26 135.888,34.812 136.9,33.8 136.9,28.698 137.198,28.4 R18.1
NetN4_27: N4.27 R10.1 | length 58.7
  Top Layer w0.254: v1(79.1,34.6) 81,34.6 82.4,36 128.462,36 N4.27
  Top Layer w0.508: R10.1 77.7,36 v1(79.1,34.6)
NetP2_1: P2.1 U7.1 U7.4 | length 19.1
  Top Layer w0.508: P2.1 24.5,86 25,85.5 25,83.852 ; U7.1 24.702,84.15 25,83.852 ; U7.4 25.298,82.25 25,82.548 25,83.852
NetP3_1: P3.1 U8.1 U8.4 | length 26
  Top Layer w0.508: P3.1 17.5,66 18,66.5 18,71.202 18.298,71.5 27.202,71.5 27.5,71.202 27.5,69.902 ; U8.1 27.202,70.2 27.5,69.902 ; U8.4 28.2,68.3 27.5,69 27.5,69.902
NetP10_2: P10.2 R39.2 U9.2 | length 6.2
  Top Layer w0.508: P10.2 143.977,44.401 R39.2 144.277,42.311 144.573,42.015 144.573,41.715 145.397,40.891 U9.2
NetP11_2: P11.2 R47.2 U16.2 | length 6.8
  Top Layer w0.508: P11.2@143.967,47.511 R47.2@146.577,47.511 ; R47.2 148.32,47.484 U16.2
NetQ1_2: Q1.2 R33.1 R36.1 | length 3.4
  Top Layer w0.305: R36.1@75.775,55.3 R33.1 ; R33.1@77.2,55.35 Q1.2
NetQ1_5: Q1.5 R35.1 R38.1 | length 3.7
  Top Layer w0.305: Q1.5 R35.1@77.2,61.55
  Top Layer w0.508: R38.1 R35.1
NetQ2_2: Q2.2 R44.1 R45.1 | length 3.6
  Top Layer w0.254: R45.1 R44.1@85.55,21.3 ; R44.1@85.55,21.35 R44.1@85.6,21.3
  Top Layer w0.305: R44.1@85.575,21.325 Q2.2@85.575,23.136
NetQ2_5: Q2.5 R43.2 R46.1 | length 3.4
  Top Layer w0.305: R46.1 R43.2 85.575,26.975 Q2.5@85.575,25.264
NetR6_1: R6.1 U1.5 | length 4.6
  Top Layer w0.254: U1.5 58.649,12.1 58.5,11.951 58.5,9.9 58.7,9.7 R6.1
NetR7_1: R7.1 U2.6 | length 2.9
  Top Layer w0.305: U2.6 31.082,11.824 31.019,11.761 31.019,10.812 31.198,10.634 31.552,10.634 31.95,10.236 R7.1
NetR14_1: R14.1 U3.9 | length 2.4
  Top Layer w0.305: U3.9 65.975,70.75 R14.1
NetR15_1: R15.1 U3.16 | length 1.3
  Top Layer w0.305: U3.16 64.127,75.3 64.15,75.323 R15.1
NetR19_1: R19.1 U3.3 | length 24.8
  Top Layer w0.305: R19.1 45.6,77.1 52.9,77.1 56,74 U3.3
NetR19_2: R19.2 R34.1 | length 7.9
  Top Layer w0.508: R34.1 26.55,77.75 27.2,77.1 R19.2
NetR20_1: R20.1 U3.7 | length 24.6
  Top Layer w0.305: R20.1 43.5,62.5 52.4,71.4 U3.7
NetR20_2: R20.2 R37.1 | length 9
  Top Layer w0.508: R37.1 28.974,62.926 29.4,62.5 R20.2
NetR41_1: R41.1 U10.5 | length 4.6
  Top Layer w0.254: U10.5 50.101,90 50.249,90.149 50.249,92.051 50.101,92.2 R41.1@48.999,92.2
pos_out: C4.2 C5.2 C6.2 C37.2 C38.2 C39.2 C40.2 C46.1 C48.2 N1.4 pad.16@68.927,18.327 U1.9 U1.10 U7.2 U8.2 U15.2 | length 39
  Top Layer w0.254: U1.9 65.95,13.6 C48.2@66.4,14.05 ; U1.10 C48.2@66.4,14.1 ; C48.2@66.4,14.2 C48.2@66.65,14.2
  Top Layer w0.508: v1(17.4,84.348) 17.402,84.35 C39.2 C40.2 21.7,83.498 21.998,83.2 U7.2 ; v1(19.924,70.398) 19.926,70.4 C38.2 C37.2 24.124,69.548 24.421,69.25 U8.2 ; C4.2@36.71,33.74 N1.4 39.26,36.09 C46.1@39.35,36 ; C4.2 36.75,31.998 37.048,31.7 v1(40.5,31.7) ; U15.2 48.553,45.3 C5.2 48.622,45.269 50.472,45.269 v1(50.503,45.3) ; C6.2 v1(66.8,16) 66.8,14.35 C48.2@66.65,14.2
REFCAP: C10.2 N3.6 | length 2
  Top Layer w0.305: C10.2@68,41.15 68.075,41.225 N3.6
REFIO: C11.2 C12.2 N3.4 N3.15 | length 10.7
  Top Layer w0.305: N3.4 71.925,42.525 73.225,43.825 N3.15 77.9,43.825 80.075,43.825 C12.2@80.1,43.85
SPI1_MISO: N3.13 N4.8 U3.8 | length 89.7
  Top Layer w0.254: U3.8 60.101,70.75 60.25,70.601 60.25,65.325 60.75,64.825 80.775,64.825 92.64,52.96 92.64,44.972 ; N3.13 75.872,42.576 77.076,42.576 77.5,43 81.728,43 83.7,44.972 92.64,44.972 ; N4.8 92.64,44.972
SPI1_MOSI: N3.10 N4.22 U3.14 | length 142.9
  Top Layer w0.254: U3.14 67.525,74 68.025,74.5 82.1,74.5 95,61.6 124.5,61.6 125.5,60.6 125.5,45.121 ; N3.10 76.825,40.575 77.2,40.2 79.8,40.2 81.3,38.7 117.3,38.7 123.572,44.972 N4.22 N4.22@131.962,45.2
SPI1_SCK: N3.12 N4.7 U3.12 | length 102.3
  Top Layer w0.254: U3.12 66.475,72.7 66.675,72.5 78.4,72.5 v2(94.6,56.3) ; N3.12 77.366,41.875 77.991,42.5 83,42.5 84.2,43.7 113.2,43.7 113.9,44.4 113.9,47.1 113.488,47.512 N4.7
  Bottom Layer w0.254: v2(94.6,56.3) 103.388,47.512 N4.7
TIA_out: K1.9 N1.6 R3.2 | length 19.2
  Top Layer w0.762: K1.9 26.454,47.08 26.9,46.634 26.9,42.246 27.346,41.8 33.7,41.8 34.17,42.27 N1.6 34.17,46.28 R3.2
pads on no net: K1.3 K1.4 K1.5 K2.3 K2.4 K2.5 K2.8 N1.1 N1.5 N1.8 N4.5 N4.14 N4.15 N4.16 N4.19 N4.24 U1.4 U2.4 U2.7 U3.2 U3.6 U10.4 U12.3 U12.7 U16.3

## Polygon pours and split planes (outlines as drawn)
GND on Top inner "NONET_L-01_P-001" (solid, pour order 0): 0,100 160,100 160,0 0,0
pos_out on Bottom inner "POS_OUT_L03_P002" (solid, pour order 2): 49,17 49,0 77,0 77,22 73,26 64,26 54,26 52,28 52,47 51,48 51,61 49,63 43,63 41,65 41,82 40,83 35,83 33.996,81.996 26.004,81.996 21,87 16,87 15,86 15,78 16,77 35,77 37,75 37,70 36,69 29,69 26,72 19,72 17,70 17,52 19,50 38,50 41,47 41,36 39,34 37,34 36,33 36,30 34,28 24,28 22,26 22,17 23,17
DVDD on Bottom inner "DVDD_L03_P007" (solid, pour order 7): 73,26 73,51 72,52 65,52 64,53 64,100 160,100 160,0 77,0 77,22
AVDD on Bottom inner "AVDD_L03_P004" (solid, pour order 4): 52,28 54,26 73,26 73,51 72,52 65,52 64,53 64,100 35,100 35,83 40,83 41,82 41,65 43,63 49,63 51,61 51,48 52,47
neg_out on Bottom inner "NEG_OUT_L03_P001" (solid, pour order 1): 22,17 49,17 49,0 0,0 0,16 0,100 35,100 35,83 33.996,81.996 26.004,81.996 21,87 16,87 15,86 15,78 16,77 35,77 37,75 37,70 36,69 29,69 26,72 19,72 17,70 17,52 19,50 38,50 41,47 41,36 39,34 37,34 36,33 36,30 34,28 24,28 22,26
no net on Top Solder (solid): 160,100 0,100 0,97 160,97
GND on Top Layer "GND_L01_P012" (solid, pour order 12): 0,100 0,97 160,97 160,100
GND on Top Layer "GND_L01_P011" (solid, pour order 11): 0,3 0,0 160,0 160,3
GND on Bottom Layer "GND_L04_P014" (solid, pour order 14): 160,3 160,0 0,0 0,3
GND on Bottom Layer "GND_L04_P013" (solid, pour order 13): 0,100 0,97 160,97 160,100

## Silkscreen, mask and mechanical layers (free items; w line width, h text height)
Top Overlay:
  drawing of 9 lines, arcs and shapes, not listed
  text "Drain" at 1.3,94.3 h1.52
  text "Sponsert by:" at 71.3,93.808 h1.52
  text "Gate" at 1.3,74.3 h1.52
  text "gnd" at 48.192,74.2 h1.52 r90
  text "AVDD" at 44.2,72.8 h1.52 r90
  text "Source" at 1.3,41.3 h1.52
  text "gnd" at 70.727,21.885 h1.52
  text "gnd" at 143.454,21.658 h1.52
  text "gnd" at 19.273,18.585 h1.52
  text "pos" at 70.7,17.908 h1.52
  text "DVDD" at 143.454,17.4 h1.52
  text "neg" at 19.3,14.408 h1.52
Top Solder:
  rectangle: 0,0 160,3
Bottom Solder:
  rectangle: -0.254,97 159.746,100
  rectangle: 0,0 160,3
Mechanical 1:
  lines w0.254: 160,0 160,100 0,100 0,0 160,0 ; 160,0 160,0
Drill Drawing:
  circle w0.203: c2.476,123.547 r0.847
  lines w0.203: 1.63,115.08 2.476,115.503 3.323,115.08 2.9,115.927 3.323,116.773 2.476,116.35 1.63,116.773 2.053,115.927 1.63,115.08 ; 1.63,118.89 3.323,118.89 3.323,120.583 1.63,120.583 1.63,118.89 ; 1.63,126.933 2.053,126.933 2.476,126.51 2.9,126.933 3.323,126.933 2.9,127.357 3.323,127.78 2.9,127.78 2.476,128.203 2.053,127.78 1.63,127.78 2.053,127.357 1.63,126.933 ; 1.63,132.013 3.323,132.013 2.476,130.32 1.63,132.013 ; 1.63,134.553 2.053,134.553 2.053,134.13 2.9,134.13 2.9,134.553 3.323,134.553 3.323,135.4 2.9,135.4 2.9,135.823 2.053,135.823 2.053,135.4 1.63,135.4 1.63,134.553 ; 1.63,137.94 1.63,138.363 2.053,138.787 1.63,139.21 1.63,139.633 2.053,139.633 2.476,139.21 2.9,139.633 3.323,139.633 3.323,139.21 2.9,138.787 3.323,138.363 3.323,137.94 2.9,137.94 2.476,138.363 2.053,137.94 1.63,137.94
  lines w0.254: 0.127,113.937 142.288,113.937 ; 0.127,140.607 142.288,140.607 ; 13.957,110.127 13.957,144.417 ; 28.837,110.127 28.837,144.417 ; 57.175,110.127 57.175,144.417 ; 69.862,110.127 69.862,144.417 ; 88.338,110.127 88.338,144.417 ; 126.325,110.127 126.325,144.417 ; 0.127,110.127 142.288,110.127 142.288,144.417 0.127,144.417 0.127,110.127
  text "Symbol" at 2.413,141.75 h1.83
  text "Count" at 15.1,141.75 h1.83
  text "Hole Size" at 29.98,141.75 h1.83
  text "Plated" at 58.318,141.75 h1.83
  text "Hole Type" at 71.005,141.75 h1.83
  text "Drill Layer Pair" at 89.481,141.75 h1.83
  text "Via/Pad" at 127.468,141.75 h1.83
  text "69" at 15.1,137.94 h1.52
  text "27,56mil (0,700mm)" at 29.98,137.94 h1.52
  text "PTH" at 58.318,137.94 h1.52
  text "Round" at 71.005,137.94 h1.52
  text "Top Layer - Bottom Layer" at 89.481,137.94 h1.52
  text "Via" at 127.468,137.94 h1.52
  text "7" at 15.1,134.13 h1.52
  text "31,50mil (0,800mm)" at 29.98,134.13 h1.52
  text "PTH" at 58.318,134.13 h1.52
  text "Round" at 71.005,134.13 h1.52
  text "Top Layer - Bottom Layer" at 89.481,134.13 h1.52
  text "Pad" at 127.468,134.13 h1.52
  text "6" at 15.1,130.32 h1.52
  text "31,50mil (0,800mm)" at 29.98,130.32 h1.52
  text "PTH" at 58.318,130.32 h1.52
  text "Round" at 71.005,130.32 h1.52
  text "Top Layer - Bottom Layer" at 89.481,130.32 h1.52
  text "Via" at 127.468,130.32 h1.52
  text "3" at 15.1,126.51 h1.52
  text "35,00mil (0,889mm)" at 29.98,126.51 h1.52
  text "PTH" at 58.318,126.51 h1.52
  text "Round" at 71.005,126.51 h1.52
  text "Top Layer - Bottom Layer" at 89.481,126.51 h1.52
  text "Pad" at 127.468,126.51 h1.52
  text "28" at 15.1,122.7 h1.52
  text "35,43mil (0,900mm)" at 29.98,122.7 h1.52
  text "PTH" at 58.318,122.7 h1.52
  text "Round" at 71.005,122.7 h1.52
  text "Top Layer - Bottom Layer" at 89.481,122.7 h1.52
  text "Pad" at 127.468,122.7 h1.52
  text "28" at 15.1,118.89 h1.52
  text "39,37mil (1,000mm)" at 29.98,118.89 h1.52
  text "PTH" at 58.318,118.89 h1.52
  text "Round" at 71.005,118.89 h1.52
  text "Top Layer - Bottom Layer" at 89.481,118.89 h1.52
  text "Pad" at 127.468,118.89 h1.52
  text "8" at 15.1,115.08 h1.52
  text "78,74mil (2,000mm)" at 29.98,115.08 h1.52
  text "PTH" at 58.318,115.08 h1.52
  text "Round" at 71.005,115.08 h1.52
  text "Top Layer - Bottom Layer" at 89.481,115.08 h1.52
  text "Pad" at 127.468,115.08 h1.52
  text "149 Total" at 15.1,111.27 h1.52

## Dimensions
160,0 to 160,81 on Mechanical 1
0,100 to 0,97 on Mechanical 1
0,0 to 0,3 on Mechanical 1
0,0 to 160,0 on Mechanical 1
0,0 to 0,100 on Mechanical 1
